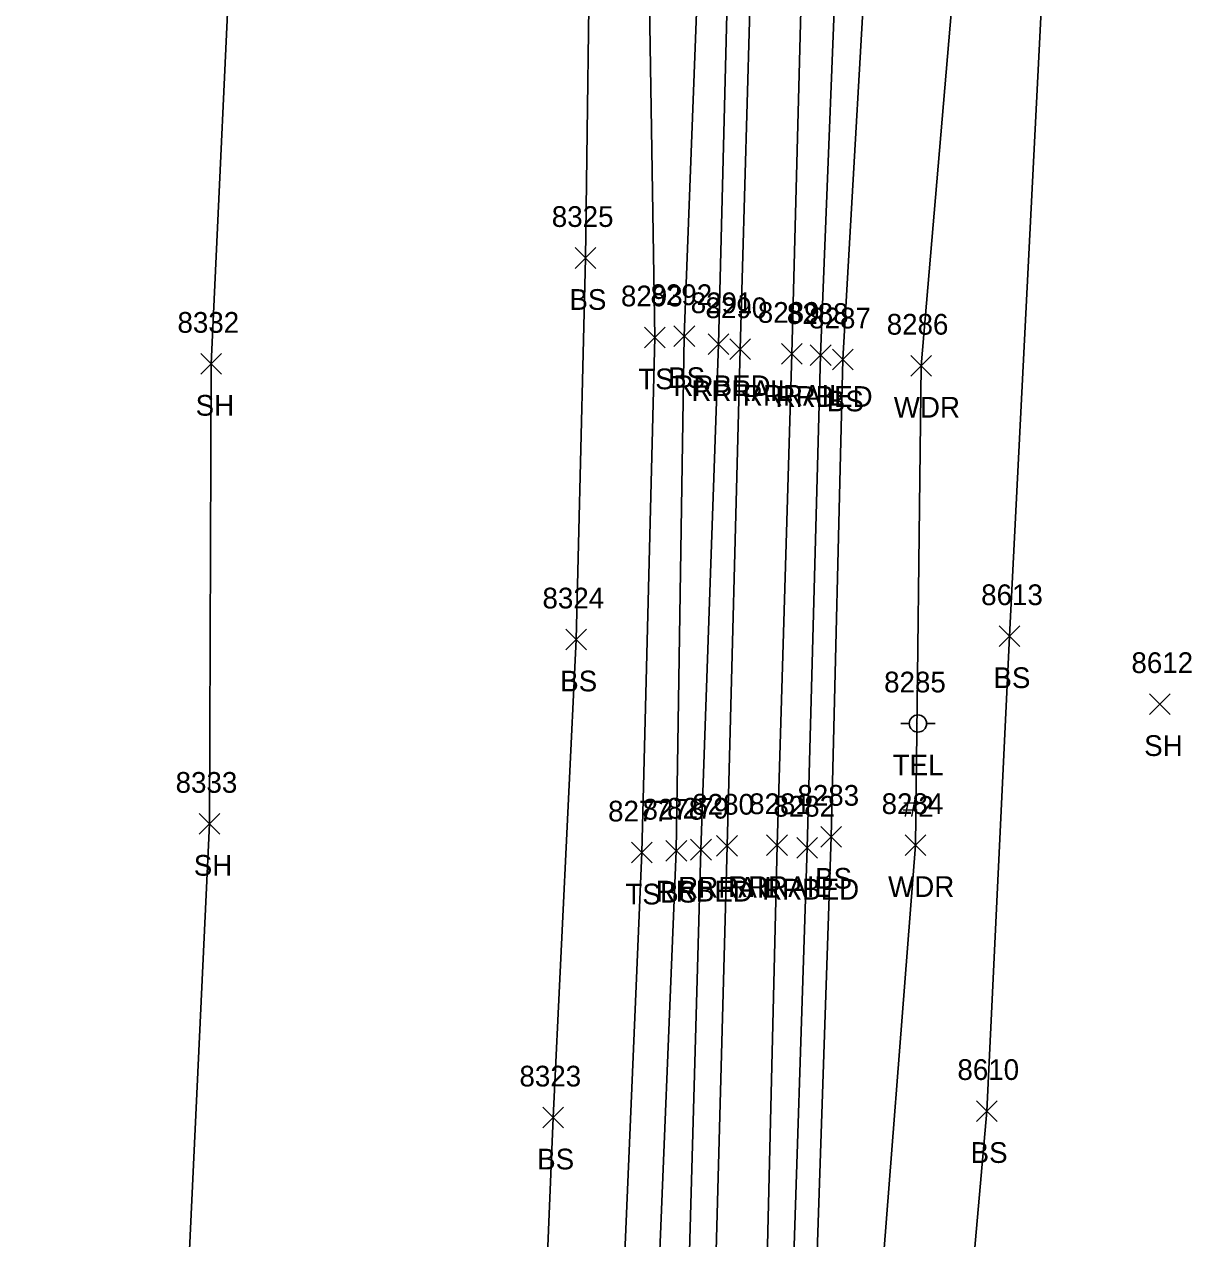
# Model space of a CAD drawing. Extents: x 1769141 to 1770911, y 735471 to 741449.
# Drawn here: x 1770212 to 1770324.5, y 737140.8 to 737257.9 of the extents above; entities that cross this region are included whole.
import ezdxf

# ---------------------------------------------------------------- set-up
doc = ezdxf.new("R2010")
doc.units = 0
for name, color, linetype in [('L_A', 7, 'Continuous'), ('L_I', 7, 'Continuous'), ('L_TIC', 7, 'Continuous'), ('LAWA', 7, 'Continuous'), ('LELB', 7, 'Continuous'), ('LSOGP', 7, 'Continuous'), ('R_A', 7, 'Continuous'), ('R_I', 7, 'Continuous'), ('R_TIC', 7, 'Continuous'), ('RR', 7, 'Continuous'), ('RRB', 7, 'Continuous'), ('U_A', 7, 'Continuous'), ('U_C', 7, 'Continuous'), ('U_I', 7, 'Continuous'), ('UP', 7, 'Continuous')]:
    doc.layers.add(name, color=color, linetype=linetype)

msp = doc.modelspace()

# ---------------------------------------------------------------- linework, layer by layer
at = {"layer": 'L_TIC'}
for points in [[(1770265.09, 737234.37), (1770267.09, 737236.37)], [(1770267.09, 737234.37), (1770265.09, 737236.37)], [(1770271.76, 737226.71), (1770273.76, 737228.71)], [(1770273.76, 737226.71), (1770271.76, 737228.71)], [(1770274.61, 737226.83), (1770276.61, 737228.83)], [(1770276.61, 737226.83), (1770274.61, 737228.83)], [(1770228.99, 737224.16), (1770230.99, 737226.16)], [(1770230.99, 737224.16), (1770228.99, 737226.16)], [(1770289.91, 737224.58), (1770291.91, 737226.58)], [(1770291.91, 737224.58), (1770289.91, 737226.58)], [(1770297.45, 737223.98), (1770299.45, 737225.98)], [(1770299.45, 737223.98), (1770297.45, 737225.98)], [(1770264.19, 737197.57), (1770266.19, 737199.57)], [(1770266.19, 737197.57), (1770264.19, 737199.57)], [(1770305.98, 737197.89), (1770307.98, 737199.89)], [(1770307.98, 737197.89), (1770305.98, 737199.89)], [(1770320.47, 737191.34), (1770322.47, 737193.34)], [(1770322.47, 737191.34), (1770320.47, 737193.34)], [(1770228.81, 737179.79), (1770230.81, 737181.79)], [(1770230.81, 737179.79), (1770228.81, 737181.79)], [(1770288.78, 737178.54), (1770290.78, 737180.54)], [(1770290.78, 737178.54), (1770288.78, 737180.54)], [(1770296.9, 737177.74), (1770298.9, 737179.74)], [(1770298.9, 737177.74), (1770296.9, 737179.74)], [(1770270.52, 737177.02), (1770272.52, 737179.02)], [(1770272.52, 737177.02), (1770270.52, 737179.02)], [(1770273.84, 737177.2), (1770275.84, 737179.2)], [(1770275.84, 737177.2), (1770273.84, 737179.2)], [(1770303.78, 737152.09), (1770305.78, 737154.09)], [(1770305.78, 737152.09), (1770303.78, 737154.09)], [(1770261.97, 737151.46), (1770263.97, 737153.46)], [(1770263.97, 737151.46), (1770261.97, 737153.46)]]:
    msp.add_lwpolyline(points, dxfattribs=at)
at = {"layer": 'LAWA'}
msp.add_lwpolyline([(1770295.56, 736765.07), (1770288.47, 736765.03), (1770285.4, 736787.87), (1770284.57, 736804.63), (1770282.38, 736833.87), (1770287.4, 736893.59), (1770286.58, 736936.63), (1770289.46, 736968.99), (1770291.49, 736986.73), (1770290, 737012.94), (1770290.58, 737048.83), (1770292.25, 737100.02), (1770294.09, 737129.48), (1770297.9, 737178.74), (1770298.45, 737224.98), (1770303.27, 737281.64), (1770303.62, 737324.77), (1770304.03, 737377.4)], dxfattribs=at)
at = {"layer": 'LELB'}
for points in [[(1770284.22, 736983.53), (1770286.1, 737006.52), (1770285.78, 737050.17), (1770287.67, 737099.53), (1770288.1, 737129.93), (1770289.78, 737179.54), (1770290.91, 737225.58), (1770293.69, 737274.35), (1770294.72, 737325.7), (1770295.85, 737386.33), (1770296.79, 737425.26), (1770298.1, 737467.61), (1770299.88, 737513.29), (1770300.86, 737550.57), (1770302.69, 737591.97), (1770303.34, 737644.67), (1770305.34, 737693.43), (1770307.48, 737738.89), (1770308.5, 737789.11), (1770309.29, 737836.41), (1770310.87, 737872.45)], [(1770269.27, 736974.12), (1770270.69, 737003.92), (1770271.03, 737053.86), (1770272.32, 737097.75), (1770272.92, 737131.76), (1770274.84, 737178.2), (1770275.61, 737227.83), (1770277.38, 737274.26), (1770278.99, 737326.74), (1770280.59, 737386.92), (1770281.43, 737425.53), (1770282.04, 737467.46), (1770283.44, 737512.78), (1770283.79, 737551.85), (1770285.35, 737592.82), (1770287.29, 737644.47), (1770288.42, 737691.85), (1770289.44, 737741.02), (1770289.98, 737788.31), (1770291.46, 737837.25)], [(1770249.46, 736962.04), (1770263.88, 736963.02), (1770266.91, 736974.5), (1770267.05, 737003.42), (1770268.31, 737053.77), (1770267.73, 737097.82), (1770269.57, 737132.6), (1770271.52, 737178.02), (1770272.76, 737227.71), (1770272.04, 737273.95), (1770277.42, 737326.8), (1770278.12, 737387.36), (1770277.35, 737426.21), (1770278.82, 737466.73), (1770278.22, 737491.37), (1770271.32, 737497.06), (1770272.28, 737508.08), (1770279.53, 737512.94), (1770280.12, 737551.03), (1770278.93, 737574.69)], [(1770292.28, 737013.24), (1770296.28, 737048.29), (1770298.58, 737101.41), (1770302.61, 737128.25), (1770304.78, 737153.09), (1770306.98, 737198.89), (1770310.91, 737276.4), (1770319.23, 737323.49), (1770312.01, 737369.68)], [(1770223.3, 736999.74), (1770247.32, 736993.47), (1770249.33, 736982.02), (1770256.99, 736968.47), (1770258.56, 736968.25), (1770259.68, 736979.83), (1770259.53, 737007.75), (1770256.82, 737041.42), (1770260.09, 737073.67), (1770260.96, 737104.34), (1770262.97, 737152.46), (1770265.19, 737198.57), (1770266.09, 737235.37), (1770266.57, 737271.78), (1770267.99, 737295.65), (1770265.74, 737320.11), (1770261.62, 737337.17)]]:
    msp.add_lwpolyline(points, dxfattribs=at)
at = {"layer": 'LSOGP'}
msp.add_lwpolyline([(1770232.14, 737271.5), (1770229.99, 737225.16), (1770229.81, 737180.79), (1770227.47, 737130.79), (1770227.93, 737090.46), (1770225.16, 737051.92), (1770220.96, 737021.3), (1770223.3, 736999.74), (1770222.78, 736985.92), (1770211.96, 736934.94)], dxfattribs=at)
at = {"layer": 'R_TIC'}
for points in [[(1770277.92, 737226.05), (1770279.92, 737228.05)], [(1770279.92, 737226.05), (1770277.92, 737228.05)], [(1770280, 737225.57), (1770282, 737227.57)], [(1770282, 737225.57), (1770280, 737227.57)], [(1770284.97, 737225.12), (1770286.97, 737227.12)], [(1770286.97, 737225.12), (1770284.97, 737227.12)], [(1770287.76, 737225.01), (1770289.76, 737227.01)], [(1770289.76, 737225.01), (1770287.76, 737227.01)], [(1770276.22, 737177.3), (1770278.22, 737179.3)], [(1770278.22, 737177.3), (1770276.22, 737179.3)], [(1770278.73, 737177.68), (1770280.73, 737179.68)], [(1770280.73, 737177.68), (1770278.73, 737179.68)], [(1770283.55, 737177.73), (1770285.55, 737179.73)], [(1770285.55, 737177.73), (1770283.55, 737179.73)], [(1770286.46, 737177.49), (1770288.46, 737179.49)], [(1770288.46, 737177.49), (1770286.46, 737179.49)]]:
    msp.add_lwpolyline(points, dxfattribs=at)
at = {"layer": 'RR'}
for points in [[(1770267.4, 736722.31), (1770268.34, 736758.82), (1770269.57, 736804.44), (1770270.45, 736834.65), (1770272.42, 736909.27), (1770273.15, 736938.32), (1770274.05, 736970.76), (1770275.07, 737005.76), (1770276.22, 737052.19), (1770277.52, 737098.47), (1770278.47, 737131.31), (1770279.73, 737178.68), (1770281, 737226.57), (1770282.34, 737274.07)], [(1770272.41, 736722.1), (1770273.29, 736759.01), (1770274.62, 736804.33), (1770275.38, 736834.93), (1770277.26, 736906.22), (1770278.11, 736938.08), (1770278.9, 736969.65), (1770279.86, 737006.36), (1770281.15, 737052.02), (1770282.49, 737099.38), (1770283.42, 737130.8), (1770284.55, 737178.73), (1770285.97, 737226.12), (1770287.25, 737273.96)]]:
    msp.add_lwpolyline(points, dxfattribs=at)
at = {"layer": 'RRB'}
for points in [[(1770264.61, 736722.25), (1770265.29, 736759.21), (1770266.68, 736803.74), (1770267.29, 736834.32), (1770268.85, 736909.78), (1770270.22, 736938.92), (1770271.46, 736972.05), (1770272.55, 737004.83), (1770273.67, 737052.68), (1770274.45, 737097.79), (1770275.89, 737131.57), (1770277.22, 737178.3), (1770278.92, 737227.05), (1770280.11, 737274.21)], [(1770275.05, 736722.18), (1770278.17, 736759.08), (1770279.42, 736805.27), (1770278.55, 736834.64), (1770280.9, 736900.53), (1770282.38, 736937.77), (1770283.59, 736969.2), (1770283.11, 737006.43), (1770283.91, 737051.19), (1770285.56, 737099.3), (1770285.88, 737130.25), (1770287.46, 737178.49), (1770288.76, 737226.01), (1770290.63, 737273.86)]]:
    msp.add_lwpolyline(points, dxfattribs=at)
at = {"layer": 'UP'}
for p, q in [((1770296.48, 737190.46), (1770297.31, 737190.46)), ((1770298.14, 737190.47), (1770298.14, 737190.47)), ((1770299.81, 737190.47), (1770298.97, 737190.47)), ((1770298.97, 737190.47), (1770298.97, 737190.47)), ((1770299.81, 737190.47), (1770299.81, 737190.47))]:
    msp.add_line(p, q, dxfattribs=at)
msp.add_circle((1770298.14, 737190.47), 0.833, dxfattribs=at)

# ---------------------------------------------------------------- texts
at = {"layer": 'L_A'}
for s, p in [('BS', (1770264.53, 737230.37)), ('TS', (1770271.17, 737222.71)), ('BS', (1770274.05, 737222.83)), ('BS', (1770289.35, 737220.58)), ('SH', (1770228.48, 737220.16)), ('WDR', (1770295.81, 737219.98)), ('BS', (1770305.42, 737193.89)), ('BS', (1770263.64, 737193.57)), ('SH', (1770319.96, 737187.34)), ('SH', (1770228.3, 737175.79)), ('BS', (1770288.22, 737174.54)), ('WDR', (1770295.26, 737173.74)), ('TS', (1770269.93, 737173.02)), ('BS', (1770273.28, 737173.2)), ('BS', (1770303.22, 737148.09)), ('BS', (1770261.42, 737147.46))]:
    msp.add_text(s, height=2, dxfattribs=at).set_placement(p)
at = {"layer": 'L_I'}
for s, p in [('8325', (1770262.83, 737238.37)), ('8293', (1770269.5, 737230.71)), ('8292', (1770272.35, 737230.83)), ('8332', (1770226.73, 737228.16)), ('8287', (1770287.65, 737228.58)), ('8286', (1770295.13, 737227.98)), ('8613', (1770304.24, 737201.89)), ('8324', (1770261.93, 737201.57)), ('8612', (1770318.73, 737195.34)), ('8333', (1770226.55, 737183.79)), ('8283', (1770286.52, 737182.54)), ('8277', (1770268.26, 737181.02)), ('8278', (1770271.58, 737181.2)), ('8284', (1770294.64, 737181.74)), ('8323', (1770259.71, 737155.46)), ('8610', (1770301.95, 737156.09))]:
    msp.add_text(s, height=2, dxfattribs=at).set_placement(p)
at = {"layer": 'R_A'}
for s, p in [('RRBED', (1770274.57, 737222.05)), ('RRRAIL', (1770276.29, 737221.57)), ('RRRAIL', (1770281.26, 737221.12)), ('RRBED', (1770284.41, 737221.01)), ('RRRAIL', (1770279.84, 737173.73)), ('RRBED', (1770272.86, 737173.3)), ('RRRAIL', (1770275.02, 737173.68)), ('RRBED', (1770283.11, 737173.49))]:
    msp.add_text(s, height=2, dxfattribs=at).set_placement(p)
at = {"layer": 'R_I'}
for s, p in [('8291', (1770276.23, 737230.05)), ('8290', (1770277.65, 737229.57)), ('8289', (1770282.7, 737229.12)), ('8288', (1770285.5, 737229.01)), ('8279', (1770273.95, 737181.3)), ('8280', (1770276.38, 737181.68)), ('8281', (1770281.86, 737181.73)), ('8282', (1770284.2, 737181.49))]:
    msp.add_text(s, height=2, dxfattribs=at).set_placement(p)
at = {"layer": 'U_A'}
msp.add_text('TEL', height=2, dxfattribs=at).set_placement((1770295.7, 737185.47))
at = {"layer": 'U_C'}
msp.add_text('#2', height=2, dxfattribs=at).set_placement((1770296.68, 737181.47))
at = {"layer": 'U_I'}
msp.add_text('8285', height=2, dxfattribs=at).set_placement((1770294.88, 737193.47))

doc.saveas('drawing.dxf')
